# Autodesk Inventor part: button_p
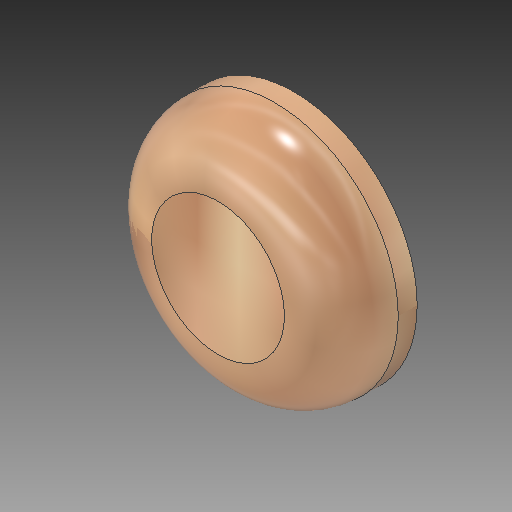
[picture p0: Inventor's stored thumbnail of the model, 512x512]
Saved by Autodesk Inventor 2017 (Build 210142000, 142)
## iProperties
Created: 2017-05
Part Number: button_p
Material: Generic
Document SubType Name: Modeling
Designer: alez_
Density: 1 g/cm^3
Appearance: Default
Author: alez_
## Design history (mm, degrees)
derived "button.ipt" dims "d0" = 9
feature "Solid1::button.ipt" dims "d0" = 9
tag "TaggingFeature1"
body "Solid1"
